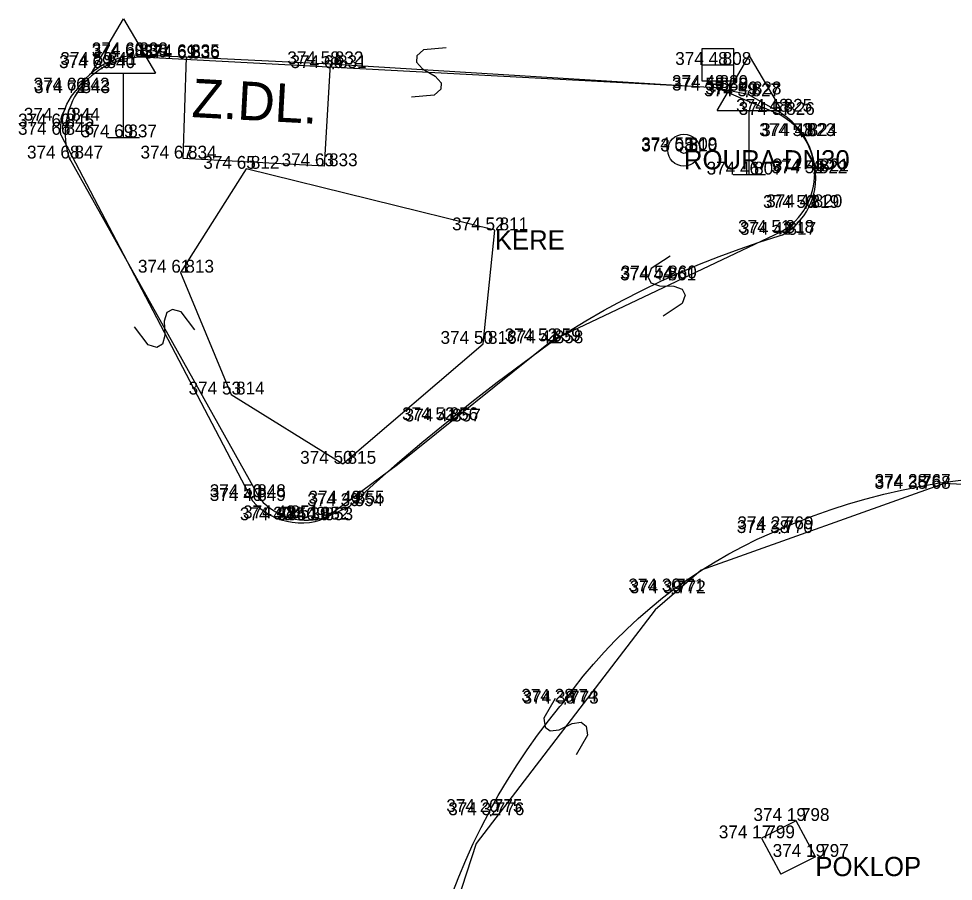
# Model space of a CAD drawing. Extents: x -601196 to -600262, y -1082523 to -1081922.
# Drawn here: x -600553.68 to -600539.1, y -1082122.59 to -1082109.14 of the extents above; entities that cross this region are included whole.
import ezdxf

# ---------------------------------------------------------------- set-up
doc = ezdxf.new("R2010")
doc.units = 0
for name, color, linetype in [('Vrstva 1', 7, 'Continuous'), ('Vrstva 10', 7, 'Continuous'), ('Vrstva 11', 7, 'Continuous'), ('Vrstva 2', 7, 'Continuous'), ('Vrstva 20', 7, 'Continuous'), ('Vrstva 21', 7, 'Continuous'), ('Vrstva 25', 7, 'Continuous'), ('Vrstva 27', 7, 'Continuous'), ('Vrstva 3', 7, 'Continuous'), ('Vrstva 34', 7, 'Continuous'), ('Vrstva 40', 7, 'Continuous'), ('Vrstva 47', 7, 'Continuous'), ('Vrstva 63', 7, 'Continuous')]:
    doc.layers.add(name, color=color, linetype=linetype)

msp = doc.modelspace()

# ---------------------------------------------------------------- linework, layer by layer
at = {"layer": 'Vrstva 1'}
for p, q in [((-600551.87, -1082109.71), (-600551.87, -1082109.71)), ((-600551.87, -1082109.74), (-600551.87, -1082109.74)), ((-600551.06, -1082109.74), (-600551.06, -1082109.74)), ((-600552.36, -1082109.86), (-600552.36, -1082109.86)), ((-600551.06, -1082109.76), (-600551.06, -1082109.76)), ((-600548.82, -1082109.85), (-600548.82, -1082109.85)), ((-600542.77, -1082109.86), (-600542.77, -1082109.86)), ((-600552.38, -1082109.91), (-600552.38, -1082109.91)), ((-600548.77, -1082109.91), (-600548.77, -1082109.91)), ((-600552.78, -1082110.26), (-600552.78, -1082110.26)), ((-600552.77, -1082110.3), (-600552.77, -1082110.3)), ((-600542.82, -1082110.22), (-600542.82, -1082110.22)), ((-600542.82, -1082110.26), (-600542.82, -1082110.26)), ((-600542.3, -1082110.32), (-600542.3, -1082110.32)), ((-600542.32, -1082110.35), (-600542.32, -1082110.35)), ((-600541.82, -1082110.59), (-600541.82, -1082110.59)), ((-600552.93, -1082110.73), (-600552.93, -1082110.73)), ((-600541.78, -1082110.64), (-600541.78, -1082110.64)), ((-600553.02, -1082110.82), (-600553.02, -1082110.82)), ((-600553.02, -1082110.95), (-600553.02, -1082110.95)), ((-600552.04, -1082110.99), (-600552.04, -1082110.99)), ((-600541.46, -1082110.97), (-600541.46, -1082110.97)), ((-600541.43, -1082110.97), (-600541.43, -1082110.97)), ((-600543.3, -1082111.19), (-600543.3, -1082111.19)), ((-600552.88, -1082111.32), (-600552.88, -1082111.32)), ((-600551.11, -1082111.32), (-600551.11, -1082111.32)), ((-600543.3, -1082111.21), (-600543.3, -1082111.21)), ((-600550.13, -1082111.48), (-600550.13, -1082111.48)), ((-600548.91, -1082111.44), (-600548.91, -1082111.44)), ((-600542.28, -1082111.57), (-600542.28, -1082111.57)), ((-600541.27, -1082111.55), (-600541.27, -1082111.55)), ((-600541.25, -1082111.52), (-600541.25, -1082111.52)), ((-600541.4, -1082112.09), (-600541.4, -1082112.09)), ((-600541.35, -1082112.08), (-600541.35, -1082112.08)), ((-600546.25, -1082112.44), (-600546.25, -1082112.44)), ((-600541.79, -1082112.48), (-600541.79, -1082112.48)), ((-600541.76, -1082112.51), (-600541.76, -1082112.51)), ((-600551.15, -1082113.1), (-600551.15, -1082113.1)), ((-600543.63, -1082113.22), (-600543.63, -1082113.22)), ((-600543.62, -1082113.19), (-600543.62, -1082113.19)), ((-600546.43, -1082114.21), (-600546.43, -1082114.21)), ((-600545.43, -1082114.17), (-600545.43, -1082114.17)), ((-600545.39, -1082114.2), (-600545.39, -1082114.2)), ((-600550.36, -1082115), (-600550.36, -1082115)), ((-600547.03, -1082115.4), (-600547.03, -1082115.4)), ((-600546.99, -1082115.42), (-600546.99, -1082115.42)), ((-600548.62, -1082116.08), (-600548.62, -1082116.08)), ((-600539.66, -1082116.44), (-600539.66, -1082116.44)), ((-600539.66, -1082116.47), (-600539.66, -1082116.47)), ((-600550.03, -1082116.6), (-600550.03, -1082116.6)), ((-600550.03, -1082116.66), (-600550.03, -1082116.66)), ((-600548.49, -1082116.7), (-600548.49, -1082116.7)), ((-600548.51, -1082116.74), (-600548.51, -1082116.74)), ((-600549.56, -1082116.96), (-600549.56, -1082116.96)), ((-600549.51, -1082116.93), (-600549.51, -1082116.93)), ((-600549.04, -1082116.95), (-600549.04, -1082116.95)), ((-600548.98, -1082116.96), (-600548.98, -1082116.96)), ((-600541.81, -1082117.16), (-600541.81, -1082117.16)), ((-600541.8, -1082117.1), (-600541.8, -1082117.1)), ((-600543.5, -1082118.07), (-600543.5, -1082118.07)), ((-600543.48, -1082118.1), (-600543.48, -1082118.1)), ((-600545.17, -1082119.79), (-600545.17, -1082119.79)), ((-600545.15, -1082119.82), (-600545.15, -1082119.82)), ((-600546.34, -1082121.51), (-600546.34, -1082121.51)), ((-600546.31, -1082121.56), (-600546.31, -1082121.56)), ((-600541.55, -1082121.65), (-600541.55, -1082121.65)), ((-600542.09, -1082121.92), (-600542.09, -1082121.92)), ((-600541.25, -1082122.21), (-600541.25, -1082122.21))]:
    msp.add_line(p, q, dxfattribs=at)
at = {"layer": 'Vrstva 10'}
for p, q in [((-600551.06, -1082109.74), (-600551.87, -1082109.71)), ((-600548.82, -1082109.85), (-600551.06, -1082109.74)), ((-600542.82, -1082110.22), (-600548.82, -1082109.85)), ((-600542.3, -1082110.32), (-600542.82, -1082110.22)), ((-600541.82, -1082110.59), (-600542.3, -1082110.32)), ((-600553.02, -1082110.95), (-600550.03, -1082116.66)), ((-600548.98, -1082116.96), (-600548.51, -1082116.74))]:
    msp.add_line(p, q, dxfattribs=at)
for points in [[(-600551.87, -1082109.71), (-600551.967, -1082109.722), (-600552.062, -1082109.741), (-600552.155, -1082109.769), (-600552.246, -1082109.803), (-600552.334, -1082109.846), (-600552.418, -1082109.895), (-600552.497, -1082109.951), (-600552.572, -1082110.013), (-600552.642, -1082110.081), (-600552.705, -1082110.155), (-600552.763, -1082110.233), (-600552.78, -1082110.26)], [(-600553.02, -1082110.95), (-600553.023, -1082110.885), (-600553.02, -1082110.818), (-600553.011, -1082110.749), (-600552.997, -1082110.679), (-600552.977, -1082110.61), (-600552.953, -1082110.542), (-600552.923, -1082110.475), (-600552.889, -1082110.411), (-600552.85, -1082110.35), (-600552.809, -1082110.294), (-600552.78, -1082110.26)], [(-600541.25, -1082111.52), (-600541.26, -1082111.424), (-600541.279, -1082111.329), (-600541.305, -1082111.236), (-600541.338, -1082111.146), (-600541.379, -1082111.058), (-600541.427, -1082110.974), (-600541.482, -1082110.894), (-600541.543, -1082110.819), (-600541.611, -1082110.75), (-600541.683, -1082110.686), (-600541.761, -1082110.628), (-600541.82, -1082110.59)], [(-600541.76, -1082112.51), (-600541.684, -1082112.463), (-600541.613, -1082112.409), (-600541.546, -1082112.35), (-600541.485, -1082112.284), (-600541.43, -1082112.214), (-600541.382, -1082112.139), (-600541.34, -1082112.06), (-600541.306, -1082111.977), (-600541.278, -1082111.892), (-600541.259, -1082111.805), (-600541.248, -1082111.717), (-600541.244, -1082111.628), (-600541.248, -1082111.539), (-600541.25, -1082111.52)], [(-600545.39, -1082114.2), (-600545.112, -1082114.022), (-600544.829, -1082113.851), (-600544.543, -1082113.686), (-600544.253, -1082113.529), (-600543.959, -1082113.378), (-600543.661, -1082113.235), (-600543.36, -1082113.098), (-600543.056, -1082112.969), (-600542.749, -1082112.847), (-600542.44, -1082112.732), (-600542.127, -1082112.625), (-600541.812, -1082112.526), (-600541.76, -1082112.51)], [(-600548.51, -1082116.74), (-600548.14, -1082116.403), (-600547.766, -1082116.072), (-600547.386, -1082115.747), (-600547, -1082115.429), (-600546.61, -1082115.116), (-600546.215, -1082114.809), (-600545.815, -1082114.509), (-600545.411, -1082114.215), (-600545.39, -1082114.2)], [(-600541.8, -1082117.1), (-600541.537, -1082116.99), (-600541.271, -1082116.888), (-600541.002, -1082116.793), (-600540.731, -1082116.706), (-600540.457, -1082116.626), (-600540.182, -1082116.554), (-600539.904, -1082116.49), (-600539.625, -1082116.433), (-600539.344, -1082116.385), (-600539.062, -1082116.344), (-600538.779, -1082116.311), (-600538.495, -1082116.286), (-600538.21, -1082116.269), (-600537.925, -1082116.26), (-600537.64, -1082116.259), (-600537.356, -1082116.266), (-600537.27, -1082116.27)], [(-600550.03, -1082116.66), (-600549.967, -1082116.725), (-600549.899, -1082116.784), (-600549.826, -1082116.836), (-600549.749, -1082116.882), (-600549.668, -1082116.921), (-600549.583, -1082116.953), (-600549.496, -1082116.977), (-600549.408, -1082116.993), (-600549.318, -1082117.001), (-600549.228, -1082117.001), (-600549.138, -1082116.994), (-600549.05, -1082116.978), (-600548.98, -1082116.96)], [(-600545.17, -1082119.79), (-600545.023, -1082119.589), (-600544.87, -1082119.393), (-600544.711, -1082119.203), (-600544.545, -1082119.017), (-600544.374, -1082118.837), (-600544.197, -1082118.662), (-600544.015, -1082118.493), (-600543.827, -1082118.33), (-600543.634, -1082118.173), (-600543.436, -1082118.022), (-600543.233, -1082117.878), (-600543.026, -1082117.74), (-600542.815, -1082117.61), (-600542.599, -1082117.485), (-600542.38, -1082117.368), (-600542.157, -1082117.258), (-600541.931, -1082117.155), (-600541.8, -1082117.1)], [(-600547.17, -1082123.59), (-600547.092, -1082123.319), (-600547.006, -1082123.051), (-600546.913, -1082122.785), (-600546.812, -1082122.521), (-600546.703, -1082122.261), (-600546.588, -1082122.004), (-600546.465, -1082121.751), (-600546.335, -1082121.5), (-600546.198, -1082121.254), (-600546.054, -1082121.012), (-600545.903, -1082120.774), (-600545.746, -1082120.54), (-600545.582, -1082120.311), (-600545.411, -1082120.087), (-600545.235, -1082119.867), (-600545.17, -1082119.79)]]:
    msp.add_lwpolyline(points, dxfattribs=at)
at = {"layer": 'Vrstva 11'}
for p, q in [((-600551.11, -1082111.32), (-600551.06, -1082109.74)), ((-600548.82, -1082109.85), (-600548.91, -1082111.44)), ((-600548.91, -1082111.44), (-600551.11, -1082111.32)), ((-600541.55, -1082121.65), (-600542.09, -1082121.92)), ((-600541.25, -1082122.21), (-600541.55, -1082121.65)), ((-600542.09, -1082121.92), (-600541.79, -1082122.48)), ((-600541.25, -1082122.21), (-600541.79, -1082122.48))]:
    msp.add_line(p, q, dxfattribs=at)
at = {"layer": 'Vrstva 20'}
for p, q in [((-600551.88, -1082109.74), (-600551.86, -1082109.74)), ((-600551.87, -1082109.725), (-600551.87, -1082109.74)), ((-600551.87, -1082109.755), (-600551.87, -1082109.74)), ((-600551.07, -1082109.76), (-600551.05, -1082109.76)), ((-600551.06, -1082109.745), (-600551.06, -1082109.76)), ((-600551.06, -1082109.775), (-600551.06, -1082109.76)), ((-600552.39, -1082109.91), (-600552.37, -1082109.91)), ((-600552.38, -1082109.895), (-600552.38, -1082109.91)), ((-600552.38, -1082109.925), (-600552.38, -1082109.91)), ((-600548.78, -1082109.91), (-600548.76, -1082109.91)), ((-600548.77, -1082109.895), (-600548.77, -1082109.91)), ((-600548.77, -1082109.925), (-600548.77, -1082109.91)), ((-600552.78, -1082110.3), (-600552.76, -1082110.3)), ((-600552.77, -1082110.285), (-600552.77, -1082110.3)), ((-600552.77, -1082110.315), (-600552.77, -1082110.3)), ((-600542.83, -1082110.26), (-600542.81, -1082110.26)), ((-600542.82, -1082110.245), (-600542.82, -1082110.26)), ((-600542.82, -1082110.275), (-600542.82, -1082110.26)), ((-600542.33, -1082110.35), (-600542.31, -1082110.35)), ((-600542.32, -1082110.335), (-600542.32, -1082110.35)), ((-600542.32, -1082110.365), (-600542.32, -1082110.35)), ((-600552.94, -1082110.73), (-600552.92, -1082110.73)), ((-600552.93, -1082110.715), (-600552.93, -1082110.73)), ((-600552.93, -1082110.745), (-600552.93, -1082110.73)), ((-600541.79, -1082110.64), (-600541.77, -1082110.64)), ((-600541.78, -1082110.625), (-600541.78, -1082110.64)), ((-600541.78, -1082110.655), (-600541.78, -1082110.64)), ((-600541.47, -1082110.97), (-600541.45, -1082110.97)), ((-600541.46, -1082110.955), (-600541.46, -1082110.97)), ((-600541.46, -1082110.985), (-600541.46, -1082110.97)), ((-600552.89, -1082111.32), (-600552.87, -1082111.32)), ((-600552.88, -1082111.305), (-600552.88, -1082111.32)), ((-600552.88, -1082111.335), (-600552.88, -1082111.32)), ((-600541.28, -1082111.55), (-600541.26, -1082111.55)), ((-600541.27, -1082111.535), (-600541.27, -1082111.55)), ((-600541.27, -1082111.565), (-600541.27, -1082111.55)), ((-600541.41, -1082112.09), (-600541.39, -1082112.09)), ((-600541.4, -1082112.075), (-600541.4, -1082112.09)), ((-600541.4, -1082112.105), (-600541.4, -1082112.09)), ((-600541.8, -1082112.48), (-600541.78, -1082112.48)), ((-600541.79, -1082112.465), (-600541.79, -1082112.48)), ((-600541.79, -1082112.495), (-600541.79, -1082112.48)), ((-600543.63, -1082113.19), (-600543.61, -1082113.19)), ((-600543.62, -1082113.175), (-600543.62, -1082113.19)), ((-600543.62, -1082113.205), (-600543.62, -1082113.19)), ((-600545.44, -1082114.17), (-600545.42, -1082114.17)), ((-600545.43, -1082114.155), (-600545.43, -1082114.17)), ((-600545.43, -1082114.185), (-600545.43, -1082114.17)), ((-600547.04, -1082115.4), (-600547.02, -1082115.4)), ((-600547.03, -1082115.385), (-600547.03, -1082115.4)), ((-600547.03, -1082115.415), (-600547.03, -1082115.4)), ((-600550.03, -1082116.585), (-600550.03, -1082116.6)), ((-600539.67, -1082116.47), (-600539.65, -1082116.47)), ((-600539.66, -1082116.455), (-600539.66, -1082116.47)), ((-600539.66, -1082116.485), (-600539.66, -1082116.47)), ((-600550.04, -1082116.6), (-600550.02, -1082116.6)), ((-600550.03, -1082116.615), (-600550.03, -1082116.6)), ((-600548.5, -1082116.7), (-600548.48, -1082116.7)), ((-600548.49, -1082116.685), (-600548.49, -1082116.7)), ((-600548.49, -1082116.715), (-600548.49, -1082116.7)), ((-600549.52, -1082116.93), (-600549.5, -1082116.93)), ((-600549.51, -1082116.915), (-600549.51, -1082116.93)), ((-600549.51, -1082116.945), (-600549.51, -1082116.93)), ((-600549.05, -1082116.95), (-600549.03, -1082116.95)), ((-600549.04, -1082116.935), (-600549.04, -1082116.95)), ((-600549.04, -1082116.965), (-600549.04, -1082116.95)), ((-600541.82, -1082117.16), (-600541.8, -1082117.16)), ((-600541.81, -1082117.145), (-600541.81, -1082117.16)), ((-600541.81, -1082117.175), (-600541.81, -1082117.16)), ((-600543.49, -1082118.1), (-600543.47, -1082118.1)), ((-600543.48, -1082118.085), (-600543.48, -1082118.1)), ((-600543.48, -1082118.115), (-600543.48, -1082118.1)), ((-600545.16, -1082119.82), (-600545.14, -1082119.82)), ((-600545.15, -1082119.805), (-600545.15, -1082119.82)), ((-600545.15, -1082119.835), (-600545.15, -1082119.82)), ((-600546.31, -1082121.545), (-600546.31, -1082121.56)), ((-600546.32, -1082121.56), (-600546.3, -1082121.56)), ((-600546.31, -1082121.575), (-600546.31, -1082121.56))]:
    msp.add_line(p, q, dxfattribs=at)
at = {"layer": 'Vrstva 21'}
for p, q in [((-600550.13, -1082111.48), (-600551.15, -1082113.1)), ((-600546.25, -1082112.44), (-600550.13, -1082111.48)), ((-600546.43, -1082114.21), (-600546.25, -1082112.44)), ((-600551.15, -1082113.1), (-600550.36, -1082115)), ((-600548.62, -1082116.08), (-600546.43, -1082114.21)), ((-600550.36, -1082115), (-600548.62, -1082116.08))]:
    msp.add_line(p, q, dxfattribs=at)
at = {"layer": 'Vrstva 25'}
for radius in [0.25, 0.05]:
    msp.add_circle((-600543.3, -1082111.19), radius, dxfattribs=at)
at = {"layer": 'Vrstva 27'}
msp.add_line((-600543.02, -1082109.86), (-600542.52, -1082109.86), dxfattribs=at)
msp.add_lwpolyline([(-600543.02, -1082110.11), (-600542.52, -1082110.11), (-600542.52, -1082109.61), (-600543.02, -1082109.61)], close=True, dxfattribs=at)
at = {"layer": 'Vrstva 34'}
for p, q in [((-600552.54, -1082109.99), (-600552.04, -1082109.14)), ((-600552.04, -1082109.14), (-600551.54, -1082109.99)), ((-600542.78, -1082110.57), (-600542.28, -1082109.72)), ((-600542.28, -1082109.72), (-600541.78, -1082110.57)), ((-600552.54, -1082109.99), (-600551.54, -1082109.99)), ((-600552.04, -1082110.99), (-600552.04, -1082109.99)), ((-600542.78, -1082110.57), (-600541.78, -1082110.57)), ((-600542.28, -1082111.57), (-600542.28, -1082110.57)), ((-600552.29, -1082110.99), (-600551.79, -1082110.99)), ((-600542.53, -1082111.57), (-600542.03, -1082111.57))]:
    msp.add_line(p, q, dxfattribs=at)
at = {"layer": 'Vrstva 47'}
for p, q in [((-600547.009, -1082109.593), (-600547.361, -1082109.625)), ((-600542.79, -1082110.22), (-600551.77, -1082109.74)), ((-600547.466, -1082109.719), (-600547.471, -1082109.819)), ((-600547.361, -1082109.625), (-600547.466, -1082109.719)), ((-600547.471, -1082109.819), (-600547.377, -1082109.924)), ((-600547.377, -1082109.924), (-600547.182, -1082110.035)), ((-600547.182, -1082110.035), (-600547.088, -1082110.14)), ((-600547.088, -1082110.14), (-600547.093, -1082110.24)), ((-600547.093, -1082110.24), (-600547.198, -1082110.334)), ((-600541.8, -1082110.64), (-600542.79, -1082110.22)), ((-600547.198, -1082110.334), (-600547.551, -1082110.366)), ((-600552.89, -1082111.31), (-600549.91, -1082116.63)), ((-600545.36, -1082114.16), (-600541.78, -1082112.46)), ((-600543.515, -1082112.841), (-600543.81, -1082113.036)), ((-600543.81, -1082113.036), (-600543.857, -1082113.169)), ((-600543.857, -1082113.169), (-600543.815, -1082113.26)), ((-600543.815, -1082113.26), (-600543.681, -1082113.307)), ((-600543.681, -1082113.307), (-600543.458, -1082113.312)), ((-600543.458, -1082113.312), (-600543.325, -1082113.359)), ((-600543.325, -1082113.359), (-600543.282, -1082113.45)), ((-600543.282, -1082113.45), (-600543.329, -1082113.583)), ((-600551.279, -1082113.673), (-600551.366, -1082113.722)), ((-600551.143, -1082113.711), (-600551.279, -1082113.673)), ((-600543.329, -1082113.583), (-600543.624, -1082113.778)), ((-600551.366, -1082113.722), (-600551.405, -1082113.858)), ((-600550.928, -1082113.992), (-600551.143, -1082113.711)), ((-600551.656, -1082114.228), (-600551.871, -1082113.947)), ((-600551.405, -1082113.858), (-600551.394, -1082114.081)), ((-600551.394, -1082114.081), (-600551.433, -1082114.217)), ((-600551.52, -1082114.266), (-600551.656, -1082114.228)), ((-600551.433, -1082114.217), (-600551.52, -1082114.266)), ((-600547.77, -1082116.09), (-600545.36, -1082114.16)), ((-600548.87, -1082116.91), (-600547.77, -1082116.09)), ((-600539.24, -1082116.39), (-600543.03, -1082117.74)), ((-600535.26, -1082116.6), (-600539.24, -1082116.39)), ((-600543.03, -1082117.74), (-600543.75, -1082118.36)), ((-600543.75, -1082118.36), (-600546.54, -1082122)), ((-600545.31, -1082119.738), (-600545.483, -1082120.046)), ((-600545.483, -1082120.046), (-600545.465, -1082120.186)), ((-600545.465, -1082120.186), (-600545.385, -1082120.247)), ((-600545.385, -1082120.247), (-600545.245, -1082120.228)), ((-600545.245, -1082120.228), (-600545.044, -1082120.131)), ((-600545.044, -1082120.131), (-600544.904, -1082120.112)), ((-600544.904, -1082120.112), (-600544.824, -1082120.173)), ((-600544.824, -1082120.173), (-600544.806, -1082120.313)), ((-600544.806, -1082120.313), (-600544.979, -1082120.621)), ((-600546.54, -1082122), (-600547.31, -1082124.36))]:
    msp.add_line(p, q, dxfattribs=at)
for centre, radius, start, end in [((-600551.759, -1082110.932), 1.192, 90.5213, 198.4724), ((-600542.306, -1082111.556), 1.046, 300.19, 61.0692), ((-600549.184, -1082116.003), 0.959, 220.7785, 289.0845)]:
    msp.add_arc(centre, radius, start, end, dxfattribs=at)

# ---------------------------------------------------------------- texts
at = {"layer": 'Vrstva 2'}
for s, p in [(' 838', (-600551.87, -1082109.71)), (' 839', (-600551.87, -1082109.74)), (' 835', (-600551.06, -1082109.74)), (' 836', (-600551.06, -1082109.76)), (' 840', (-600552.38, -1082109.91)), (' 841', (-600552.36, -1082109.86)), (' 832', (-600548.82, -1082109.85)), (' 831', (-600548.77, -1082109.91)), (' 808', (-600542.77, -1082109.86)), (' 829', (-600542.82, -1082110.22)), (' 842', (-600552.78, -1082110.26)), (' 843', (-600552.77, -1082110.3)), (' 830', (-600542.82, -1082110.26)), (' 827', (-600542.32, -1082110.35)), (' 828', (-600542.3, -1082110.32)), (' 825', (-600541.82, -1082110.59)), (' 826', (-600541.78, -1082110.64)), (' 845', (-600553.02, -1082110.82)), (' 844', (-600552.93, -1082110.73)), (' 846', (-600553.02, -1082110.95)), (' 837', (-600552.04, -1082110.99)), (' 823', (-600541.46, -1082110.97)), (' 824', (-600541.43, -1082110.97)), (' 809', (-600543.3, -1082111.19)), (' 810', (-600543.3, -1082111.21)), (' 847', (-600552.88, -1082111.32)), (' 834', (-600551.11, -1082111.32)), (' 812', (-600550.13, -1082111.48)), (' 833', (-600548.91, -1082111.44)), (' 821', (-600541.25, -1082111.52)), (' 807', (-600542.28, -1082111.57)), (' 822', (-600541.27, -1082111.55)), (' 819', (-600541.4, -1082112.09)), (' 820', (-600541.35, -1082112.08)), (' 811', (-600546.25, -1082112.44)), (' 818', (-600541.79, -1082112.48)), (' 817', (-600541.76, -1082112.51)), (' 813', (-600551.15, -1082113.1)), (' 861', (-600543.63, -1082113.22)), (' 860', (-600543.62, -1082113.19)), (' 859', (-600545.43, -1082114.17)), (' 816', (-600546.43, -1082114.21)), (' 858', (-600545.39, -1082114.2)), (' 814', (-600550.36, -1082115)), (' 856', (-600547.03, -1082115.4)), (' 857', (-600546.99, -1082115.42)), (' 815', (-600548.62, -1082116.08)), (' 767', (-600539.66, -1082116.44)), (' 768', (-600539.66, -1082116.47)), (' 848', (-600550.03, -1082116.6)), (' 849', (-600550.03, -1082116.66)), (' 854', (-600548.51, -1082116.74)), (' 855', (-600548.49, -1082116.7)), (' 851', (-600549.51, -1082116.93)), (' 850', (-600549.56, -1082116.96)), (' 852', (-600549.04, -1082116.95)), (' 853', (-600548.98, -1082116.96)), (' 770', (-600541.81, -1082117.16)), (' 769', (-600541.8, -1082117.1)), (' 771', (-600543.5, -1082118.07)), (' 772', (-600543.48, -1082118.1)), (' 774', (-600545.17, -1082119.79)), (' 773', (-600545.15, -1082119.82)), (' 775', (-600546.34, -1082121.51)), (' 776', (-600546.31, -1082121.56)), (' 798', (-600541.55, -1082121.65)), (' 799', (-600542.09, -1082121.92)), (' 797', (-600541.25, -1082122.21))]:
    msp.add_text(s, height=0.2, dxfattribs=at).set_placement(p)
at = {"layer": 'Vrstva 3'}
for s, p in [('374 60 ', (-600552.536, -1082109.71)), ('374 68 ', (-600552.536, -1082109.74)), ('374 61 ', (-600551.726, -1082109.74)), ('374 69 ', (-600551.726, -1082109.76)), ('374 69 ', (-600553.046, -1082109.91)), ('374 59 ', (-600553.026, -1082109.86)), ('374 58 ', (-600549.486, -1082109.85)), ('374 66 ', (-600549.436, -1082109.91)), ('374 48 ', (-600543.436, -1082109.86)), ('374 48 ', (-600543.486, -1082110.22)), ('374 60 ', (-600553.446, -1082110.26)), ('374 71 ', (-600553.436, -1082110.3)), ('374 59 ', (-600543.486, -1082110.26)), ('374 58 ', (-600542.986, -1082110.35)), ('374 49 ', (-600542.966, -1082110.32)), ('374 48 ', (-600542.486, -1082110.59)), ('374 57 ', (-600542.446, -1082110.64)), ('374 60 ', (-600553.686, -1082110.82)), ('374 70 ', (-600553.596, -1082110.73)), ('374 66 ', (-600553.686, -1082110.95)), ('374 69 ', (-600552.706, -1082110.99)), ('374 53 ', (-600542.126, -1082110.97)), ('374 48 ', (-600542.096, -1082110.97)), ('374 55 ', (-600543.966, -1082111.19)), ('373 08 ', (-600543.966, -1082111.21)), ('374 68 ', (-600553.546, -1082111.32)), ('374 67 ', (-600551.776, -1082111.32)), ('374 65 ', (-600550.796, -1082111.48)), ('374 63 ', (-600549.576, -1082111.44)), ('374 45 ', (-600541.916, -1082111.52)), ('374 46 ', (-600542.946, -1082111.57)), ('374 52 ', (-600541.936, -1082111.55)), ('374 50 ', (-600542.066, -1082112.09)), ('374 41 ', (-600542.016, -1082112.08)), ('374 52 ', (-600546.916, -1082112.44)), ('374 51 ', (-600542.456, -1082112.48)), ('374 42 ', (-600542.426, -1082112.51)), ('374 61 ', (-600551.816, -1082113.1)), ('374 44 ', (-600544.296, -1082113.22)), ('374 54 ', (-600544.286, -1082113.19)), ('374 52 ', (-600546.096, -1082114.17)), ('374 50 ', (-600547.096, -1082114.21)), ('374 41 ', (-600546.056, -1082114.2)), ('374 53 ', (-600551.026, -1082115)), ('374 52 ', (-600547.696, -1082115.4)), ('374 41 ', (-600547.656, -1082115.42)), ('374 50 ', (-600549.286, -1082116.08)), ('374 28 ', (-600540.326, -1082116.44)), ('374 35 ', (-600540.326, -1082116.47)), ('374 50 ', (-600550.696, -1082116.6)), ('374 40 ', (-600550.696, -1082116.66)), ('374 39 ', (-600549.176, -1082116.74)), ('374 49 ', (-600549.156, -1082116.7)), ('374 48 ', (-600550.176, -1082116.93)), ('374 40 ', (-600550.226, -1082116.96)), ('374 49 ', (-600549.706, -1082116.95)), ('374 39 ', (-600549.646, -1082116.96)), ('374 38 ', (-600542.476, -1082117.16)), ('374 27 ', (-600542.466, -1082117.1)), ('374 30 ', (-600544.166, -1082118.07)), ('374 39 ', (-600544.146, -1082118.1)), ('374 28 ', (-600545.836, -1082119.79)), ('374 38 ', (-600545.816, -1082119.82)), ('374 20 ', (-600547.006, -1082121.51)), ('374 32 ', (-600546.976, -1082121.56)), ('374 19 ', (-600542.216, -1082121.65)), ('374 17 ', (-600542.756, -1082121.92)), ('374 19 ', (-600541.916, -1082122.21))]:
    msp.add_text(s, height=0.2, dxfattribs=at).set_placement(p)
at = {"layer": 'Vrstva 40'}
msp.add_text('Z.DL.', height=0.6, rotation=356.8779, dxfattribs=at).set_placement((-600550.986, -1082110.673))
at = {"layer": 'Vrstva 63'}
for s, p in [('ROURA DN30', (-600543.3, -1082111.49)), ('KERE', (-600546.25, -1082112.74)), ('POKLOP', (-600541.25, -1082122.51))]:
    msp.add_text(s, height=0.3, dxfattribs=at).set_placement(p)

doc.saveas('drawing.dxf')
